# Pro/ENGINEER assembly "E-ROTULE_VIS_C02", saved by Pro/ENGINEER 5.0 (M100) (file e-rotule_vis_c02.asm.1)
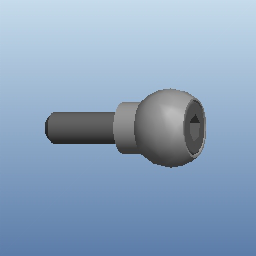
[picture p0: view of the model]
Units: millimeter Newton Second (mmNs); MM, TONNE, HOURS

Other components: 80025000-ROTULE_STD, VIS_CHC_M-4X16

Other named items: A-DROITE, A-DESSUS, A-FACE, A-R0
